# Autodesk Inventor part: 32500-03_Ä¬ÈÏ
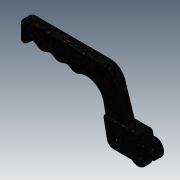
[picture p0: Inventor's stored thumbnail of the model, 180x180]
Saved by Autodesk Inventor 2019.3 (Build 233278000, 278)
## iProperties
Created: 2010-06
Part Number: 32500-03_Ä¬ÈÏ
Material: Ogólny
Document SubType Name: Modeling
Designer: CADENGINEERING4
Density: 1 g/cm^3
Appearance: Czarny
Author: CADENGINEERING4
Revision Number: ÈÎºÎ
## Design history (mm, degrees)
feature "NONE"
node "Bryła1"
